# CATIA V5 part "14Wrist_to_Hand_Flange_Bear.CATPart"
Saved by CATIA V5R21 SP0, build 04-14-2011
Part number: Wrist_to_Hand_Flange_Bear
Bounding box of the stored display mesh (mm): x -7.8 to 7.8, y -7.8 to 7.8, z 0 to 4
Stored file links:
  C:\Users\水心\Desktop\arm\Arm_Detailed_Design\Wrist_to_Hand_Flange_Bear.CATPart
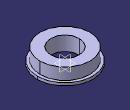
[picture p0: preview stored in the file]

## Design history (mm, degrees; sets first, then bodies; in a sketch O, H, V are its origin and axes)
Body1 (main body)
  Sketch1 on xy-plane, origin (0, 0, 0), H (1, 0, 0), V (0, 1, 0)
    circle A1 centre (0, 0) radius 7.8
    radius A1 = 7.8
  Pad1: profile Sketch1, direction (0, 0, 1), length 0.78
  Sketch2 on end face of Pad1, origin (0, 0, 0.78), H (1, 0, 0), V (0, 1, 0)
    circle A1 centre (0, 0) radius 7
    radius A1 = 7
  Pad2: profile Sketch2, direction (0, 0, 1), length 3.22
  Sketch3 on end face of Pad2, origin (0, 0, 4), H (1, 0, 0), V (0, 1, 0)
    circle A1 centre (0, 0) radius 4
    radius A1 = 4
  Pocket1: profile Sketch3, direction (0, 0, -1), through (limit type 3)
